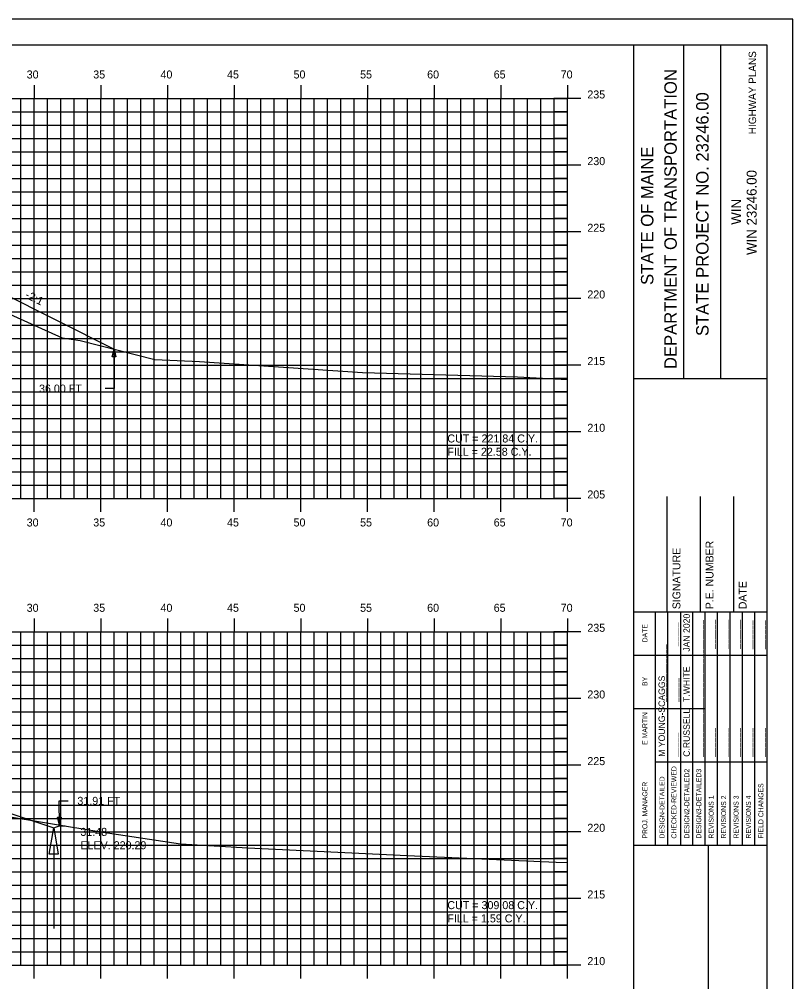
# Model space of a CAD drawing. Extents: x 1137876 to 1138046, y 608981 to 609091.
# Drawn here: x 1137988.1 to 1138046.1, y 609019.1 to 609091.3 of the extents above; entities that cross this region are included whole.
import ezdxf

# ---------------------------------------------------------------- set-up
doc = ezdxf.new("R2010")
doc.units = 0
for name, color, linetype in [('ANNOTATION', 7, 'Continuous'), ('BORDER', 7, 'Continuous'), ('D_Drainage_Ditch_Line', 7, 'Continuous'), ('D_Roadway_SlopeLines', 7, 'Continuous'), ('D_Text_Standard', 7, 'Continuous'), ('H_V ANNOTATION', 7, 'Continuous'), ('HIGHWAY_TITLE', 7, 'Continuous'), ('MAJOR', 7, 'Continuous'), ('MINOR', 7, 'Continuous'), ('PLOT BOUNDARY', 7, 'Continuous'), ('S_Roadway_Centerline', 7, 'Continuous')]:
    doc.layers.add(name, color=color, linetype=linetype)

msp = doc.modelspace()

# ---------------------------------------------------------------- linework, layer by layer
msp.add_lwpolyline([(1137924.31, 609071.229), (1137926.339, 609071.906), (1137929.339, 609072.906), (1137936.714, 609075.364), (1137936.715, 609075.364), (1137948.166, 609075.822), (1137959.166, 609076.042), (1137970.166, 609075.822), (1137977.166, 609075.542), (1137982.083, 609073.084), (1137986.552, 609070.849), (1137995.165, 609066.543)])
at = {"layer": 'BORDER'}
for p, q in [((1138034.166, 608984.335), (1138034.166, 609089.335)), ((1138037.895, 609064.332), (1138037.895, 609089.332)), ((1138040.69, 609064.332), (1138040.69, 609089.332)), ((1138034.167, 609064.329), (1138044.166, 609064.329)), ((1138036.666, 609046.838), (1138036.666, 609055.485)), ((1138039.166, 609046.838), (1138039.166, 609055.485)), ((1138041.666, 609046.838), (1138041.666, 609055.485)), ((1138034.166, 609046.838), (1138044.166, 609046.838)), ((1138034.166, 609029.338), (1138044.166, 609029.338)), ((1138039.757, 608994.338), (1138039.757, 609029.338))]:
    msp.add_line(p, q, dxfattribs=at)
msp.add_lwpolyline([(1137884.166, 608984.335), (1138044.166, 608984.335), (1138044.166, 609089.335), (1137884.166, 609089.335)], close=True, dxfattribs=at)
for points in [[(1138035.781, 609043.588), (1138035.781, 609046.838)], [(1138036.714, 609029.341), (1138036.714, 609046.838)], [(1138037.645, 609046.838), (1138037.645, 609029.341)], [(1138038.577, 609029.341), (1138038.577, 609046.838)], [(1138039.509, 609029.341), (1138039.509, 609046.838)], [(1138040.44, 609029.341), (1138040.44, 609046.838)], [(1138041.372, 609029.341), (1138041.372, 609046.838)], [(1138042.304, 609029.341), (1138042.304, 609046.838)], [(1138043.235, 609029.341), (1138043.235, 609046.838)], [(1138035.782, 609029.341), (1138035.782, 609046.132)], [(1138034.166, 609043.588), (1138044.166, 609043.588)], [(1138034.166, 609039.588), (1138035.782, 609039.588)], [(1138035.781, 609039.588), (1138039.508, 609039.588)], [(1138035.781, 609035.588), (1138044.166, 609035.588)]]:
    msp.add_lwpolyline(points, dxfattribs=at)
at = {"layer": 'D_Drainage_Ditch_Line'}
msp.add_line((1137990.642, 609029.316), (1137990.641, 609023.072), dxfattribs=at)
msp.add_lwpolyline([(1137990.97, 609028.66), (1137990.314, 609028.66), (1137990.642, 609030.628)], close=True, dxfattribs=at)
at = {"layer": 'D_Roadway_SlopeLines'}
for points in [[(1137986.552, 609070.849), (1137995.165, 609066.543)], [(1137984.698, 609032.609), (1137990.642, 609030.628)], [(1137990.642, 609030.628), (1137990.857, 609030.718), (1137991.072, 609030.771), (1137991.287, 609030.789), (1137991.502, 609030.771)]]:
    msp.add_lwpolyline(points, dxfattribs=at)
at = {"layer": 'D_Text_Standard'}
for points in [[(1137995.165, 609066.543), (1137995.184, 609063.575), (1137994.504, 609063.575)], [(1137991.072, 609030.843), (1137991.058, 609032.656), (1137991.738, 609032.656)]]:
    msp.add_lwpolyline(points, dxfattribs=at)
for points in [[(1137995.165, 609066.543), (1137995.314, 609065.961), (1137995.023, 609065.96)], [(1137991.072, 609030.843), (1137990.922, 609031.424), (1137991.213, 609031.426)]]:
    msp.add_lwpolyline(points, close=True, dxfattribs=at)
at = {"layer": 'MAJOR'}
for p, q in [((1137989.166, 609086.337), (1137989.166, 609085.335)), ((1137994.166, 609086.337), (1137994.166, 609085.335)), ((1137999.166, 609086.337), (1137999.166, 609085.335)), ((1138004.166, 609086.337), (1138004.166, 609085.335)), ((1138009.166, 609086.337), (1138009.166, 609085.335)), ((1138014.166, 609086.337), (1138014.166, 609085.335)), ((1138019.166, 609086.337), (1138019.166, 609085.335)), ((1138024.166, 609086.337), (1138024.166, 609085.335)), ((1138029.166, 609086.337), (1138029.166, 609085.335)), ((1137889.166, 609085.335), (1138029.166, 609085.335)), ((1137889.166, 609085.335), (1138029.166, 609085.335)), ((1137989.166, 609055.335), (1137989.166, 609085.335)), ((1137994.166, 609055.335), (1137994.166, 609085.335)), ((1137999.166, 609055.335), (1137999.166, 609085.335)), ((1138004.166, 609055.335), (1138004.166, 609085.335)), ((1138009.166, 609055.335), (1138009.166, 609085.335)), ((1138014.166, 609055.335), (1138014.166, 609085.335)), ((1138019.166, 609055.335), (1138019.166, 609085.335)), ((1138024.166, 609055.335), (1138024.166, 609085.335)), ((1138030.168, 609085.335), (1138028.164, 609085.335)), ((1138029.166, 609055.335), (1138029.166, 609085.335)), ((1138029.166, 609055.335), (1138029.166, 609085.335)), ((1137889.166, 609080.335), (1138029.166, 609080.335)), ((1138030.168, 609080.335), (1138028.164, 609080.335)), ((1137889.166, 609075.335), (1138029.166, 609075.335)), ((1138030.168, 609075.335), (1138028.164, 609075.335)), ((1137889.166, 609070.335), (1138029.166, 609070.335)), ((1138030.168, 609070.335), (1138028.164, 609070.335)), ((1137889.166, 609065.335), (1138029.166, 609065.335)), ((1138030.168, 609065.335), (1138028.164, 609065.335)), ((1137889.166, 609060.335), (1138029.166, 609060.335)), ((1138030.168, 609060.335), (1138028.164, 609060.335)), ((1137889.166, 609055.335), (1138029.166, 609055.335)), ((1137889.166, 609055.335), (1138029.166, 609055.335)), ((1137989.166, 609054.333), (1137989.166, 609055.335)), ((1137994.166, 609054.333), (1137994.166, 609055.335)), ((1137999.166, 609054.333), (1137999.166, 609055.335)), ((1138004.166, 609054.333), (1138004.166, 609055.335)), ((1138009.166, 609054.333), (1138009.166, 609055.335)), ((1138014.166, 609054.333), (1138014.166, 609055.335)), ((1138019.166, 609054.333), (1138019.166, 609055.335)), ((1138024.166, 609054.333), (1138024.166, 609055.335)), ((1138030.168, 609055.335), (1138028.164, 609055.335)), ((1138029.166, 609054.333), (1138029.166, 609055.335)), ((1137989.166, 609046.337), (1137989.166, 609045.335)), ((1137994.166, 609046.337), (1137994.166, 609045.335)), ((1137999.166, 609046.337), (1137999.166, 609045.335)), ((1138004.166, 609046.337), (1138004.166, 609045.335)), ((1138009.166, 609046.337), (1138009.166, 609045.335)), ((1138014.166, 609046.337), (1138014.166, 609045.335)), ((1138019.166, 609046.337), (1138019.166, 609045.335)), ((1138024.166, 609046.337), (1138024.166, 609045.335)), ((1138029.166, 609046.337), (1138029.166, 609045.335)), ((1137889.166, 609045.335), (1138029.166, 609045.335)), ((1137889.166, 609045.335), (1138029.166, 609045.335)), ((1137989.166, 609020.335), (1137989.166, 609045.335)), ((1137994.166, 609020.335), (1137994.166, 609045.335)), ((1137999.166, 609020.335), (1137999.166, 609045.335)), ((1138004.166, 609020.335), (1138004.166, 609045.335)), ((1138009.166, 609020.335), (1138009.166, 609045.335)), ((1138014.166, 609020.335), (1138014.166, 609045.335)), ((1138019.166, 609020.335), (1138019.166, 609045.335)), ((1138024.166, 609020.335), (1138024.166, 609045.335)), ((1138030.168, 609045.335), (1138028.164, 609045.335)), ((1138029.166, 609020.335), (1138029.166, 609045.335)), ((1138029.166, 609020.335), (1138029.166, 609045.335)), ((1137889.166, 609040.335), (1138029.166, 609040.335)), ((1138030.168, 609040.335), (1138028.164, 609040.335)), ((1137889.166, 609035.335), (1138029.166, 609035.335)), ((1138030.168, 609035.335), (1138028.164, 609035.335)), ((1137889.166, 609030.335), (1138029.166, 609030.335)), ((1138030.168, 609030.335), (1138028.164, 609030.335)), ((1137889.166, 609025.335), (1138029.166, 609025.335)), ((1138030.168, 609025.335), (1138028.164, 609025.335)), ((1137889.166, 609020.335), (1138029.166, 609020.335)), ((1137889.166, 609020.335), (1138029.166, 609020.335)), ((1137989.166, 609019.333), (1137989.166, 609020.335)), ((1137994.166, 609019.333), (1137994.166, 609020.335)), ((1137999.166, 609019.333), (1137999.166, 609020.335)), ((1138004.166, 609019.333), (1138004.166, 609020.335)), ((1138009.166, 609019.333), (1138009.166, 609020.335)), ((1138014.166, 609019.333), (1138014.166, 609020.335)), ((1138019.166, 609019.333), (1138019.166, 609020.335)), ((1138024.166, 609019.333), (1138024.166, 609020.335)), ((1138030.168, 609020.335), (1138028.164, 609020.335)), ((1138029.166, 609019.333), (1138029.166, 609020.335))]:
    msp.add_line(p, q, dxfattribs=at)
at = {"layer": 'MINOR'}
for p, q in [((1137988.166, 609055.335), (1137988.166, 609085.335)), ((1137990.166, 609055.335), (1137990.166, 609085.335)), ((1137991.166, 609055.335), (1137991.166, 609085.335)), ((1137992.166, 609055.335), (1137992.166, 609085.335)), ((1137993.166, 609055.335), (1137993.166, 609085.335)), ((1137995.166, 609055.335), (1137995.166, 609085.335)), ((1137996.166, 609055.335), (1137996.166, 609085.335)), ((1137997.166, 609055.335), (1137997.166, 609085.335)), ((1137998.166, 609055.335), (1137998.166, 609085.335)), ((1138000.166, 609055.335), (1138000.166, 609085.335)), ((1138001.166, 609055.335), (1138001.166, 609085.335)), ((1138002.166, 609055.335), (1138002.166, 609085.335)), ((1138003.166, 609055.335), (1138003.166, 609085.335)), ((1138005.166, 609055.335), (1138005.166, 609085.335)), ((1138006.166, 609055.335), (1138006.166, 609085.335)), ((1138007.166, 609055.335), (1138007.166, 609085.335)), ((1138008.166, 609055.335), (1138008.166, 609085.335)), ((1138010.166, 609055.335), (1138010.166, 609085.335)), ((1138011.166, 609055.335), (1138011.166, 609085.335)), ((1138012.166, 609055.335), (1138012.166, 609085.335)), ((1138013.166, 609055.335), (1138013.166, 609085.335)), ((1138015.166, 609055.335), (1138015.166, 609085.335)), ((1138016.166, 609055.335), (1138016.166, 609085.335)), ((1138017.166, 609055.335), (1138017.166, 609085.335)), ((1138018.166, 609055.335), (1138018.166, 609085.335)), ((1138020.166, 609055.335), (1138020.166, 609085.335)), ((1138021.166, 609055.335), (1138021.166, 609085.335)), ((1138022.166, 609055.335), (1138022.166, 609085.335)), ((1138023.166, 609055.335), (1138023.166, 609085.335)), ((1138025.166, 609055.335), (1138025.166, 609085.335)), ((1138026.166, 609055.335), (1138026.166, 609085.335)), ((1138027.166, 609055.335), (1138027.166, 609085.335)), ((1138028.166, 609055.335), (1138028.166, 609085.335)), ((1137889.166, 609084.335), (1138029.166, 609084.335)), ((1138029.166, 609084.335), (1138028.164, 609084.335)), ((1137889.166, 609083.335), (1138029.166, 609083.335)), ((1138029.166, 609083.335), (1138028.164, 609083.335)), ((1137889.166, 609082.335), (1138029.166, 609082.335)), ((1138029.166, 609082.335), (1138028.164, 609082.335)), ((1137889.166, 609081.335), (1138029.166, 609081.335)), ((1138029.166, 609081.335), (1138028.164, 609081.335)), ((1137889.166, 609079.335), (1138029.166, 609079.335)), ((1138029.166, 609079.335), (1138028.164, 609079.335)), ((1137889.166, 609078.335), (1138029.166, 609078.335)), ((1138029.166, 609078.335), (1138028.164, 609078.335)), ((1137889.166, 609077.335), (1138029.166, 609077.335)), ((1138029.166, 609077.335), (1138028.164, 609077.335)), ((1137889.166, 609076.335), (1138029.166, 609076.335)), ((1138029.166, 609076.335), (1138028.164, 609076.335)), ((1137889.166, 609074.335), (1138029.166, 609074.335)), ((1138029.166, 609074.335), (1138028.164, 609074.335)), ((1137889.166, 609073.335), (1138029.166, 609073.335)), ((1138029.166, 609073.335), (1138028.164, 609073.335)), ((1137889.166, 609072.335), (1138029.166, 609072.335)), ((1138029.166, 609072.335), (1138028.164, 609072.335)), ((1137889.166, 609071.335), (1138029.166, 609071.335)), ((1138029.166, 609071.335), (1138028.164, 609071.335)), ((1137889.166, 609069.335), (1138029.166, 609069.335)), ((1138029.166, 609069.335), (1138028.164, 609069.335)), ((1137889.166, 609068.335), (1138029.166, 609068.335)), ((1138029.166, 609068.335), (1138028.164, 609068.335)), ((1137889.166, 609067.335), (1138029.166, 609067.335)), ((1138029.166, 609067.335), (1138028.164, 609067.335)), ((1137889.166, 609066.335), (1138029.166, 609066.335)), ((1138029.166, 609066.335), (1138028.164, 609066.335)), ((1137889.166, 609064.335), (1138029.166, 609064.335)), ((1138029.166, 609064.335), (1138028.164, 609064.335)), ((1137889.166, 609063.335), (1138029.166, 609063.335)), ((1138029.166, 609063.335), (1138028.164, 609063.335)), ((1137889.166, 609062.335), (1138029.166, 609062.335)), ((1138029.166, 609062.335), (1138028.164, 609062.335)), ((1137889.166, 609061.335), (1138029.166, 609061.335)), ((1138029.166, 609061.335), (1138028.164, 609061.335)), ((1137889.166, 609059.335), (1138029.166, 609059.335)), ((1138029.166, 609059.335), (1138028.164, 609059.335)), ((1137889.166, 609058.335), (1138029.166, 609058.335)), ((1138029.166, 609058.335), (1138028.164, 609058.335)), ((1137889.166, 609057.335), (1138029.166, 609057.335)), ((1138029.166, 609057.335), (1138028.164, 609057.335)), ((1137889.166, 609056.335), (1138029.166, 609056.335)), ((1138029.166, 609056.335), (1138028.164, 609056.335)), ((1137988.166, 609020.335), (1137988.166, 609045.335)), ((1137990.166, 609020.335), (1137990.166, 609045.335)), ((1137991.166, 609020.335), (1137991.166, 609045.335)), ((1137992.166, 609020.335), (1137992.166, 609045.335)), ((1137993.166, 609020.335), (1137993.166, 609045.335)), ((1137995.166, 609020.335), (1137995.166, 609045.335)), ((1137996.166, 609020.335), (1137996.166, 609045.335)), ((1137997.166, 609020.335), (1137997.166, 609045.335)), ((1137998.166, 609020.335), (1137998.166, 609045.335)), ((1138000.166, 609020.335), (1138000.166, 609045.335)), ((1138001.166, 609020.335), (1138001.166, 609045.335)), ((1138002.166, 609020.335), (1138002.166, 609045.335)), ((1138003.166, 609020.335), (1138003.166, 609045.335)), ((1138005.166, 609020.335), (1138005.166, 609045.335)), ((1138006.166, 609020.335), (1138006.166, 609045.335)), ((1138007.166, 609020.335), (1138007.166, 609045.335)), ((1138008.166, 609020.335), (1138008.166, 609045.335)), ((1138010.166, 609020.335), (1138010.166, 609045.335)), ((1138011.166, 609020.335), (1138011.166, 609045.335)), ((1138012.166, 609020.335), (1138012.166, 609045.335)), ((1138013.166, 609020.335), (1138013.166, 609045.335)), ((1138015.166, 609020.335), (1138015.166, 609045.335)), ((1138016.166, 609020.335), (1138016.166, 609045.335)), ((1138017.166, 609020.335), (1138017.166, 609045.335)), ((1138018.166, 609020.335), (1138018.166, 609045.335)), ((1138020.166, 609020.335), (1138020.166, 609045.335)), ((1138021.166, 609020.335), (1138021.166, 609045.335)), ((1138022.166, 609020.335), (1138022.166, 609045.335)), ((1138023.166, 609020.335), (1138023.166, 609045.335)), ((1138025.166, 609020.335), (1138025.166, 609045.335)), ((1138026.166, 609020.335), (1138026.166, 609045.335)), ((1138027.166, 609020.335), (1138027.166, 609045.335)), ((1138028.166, 609020.335), (1138028.166, 609045.335)), ((1137889.166, 609044.335), (1138029.166, 609044.335)), ((1138029.166, 609044.335), (1138028.164, 609044.335)), ((1137889.166, 609043.335), (1138029.166, 609043.335)), ((1138029.166, 609043.335), (1138028.164, 609043.335)), ((1137889.166, 609042.335), (1138029.166, 609042.335)), ((1138029.166, 609042.335), (1138028.164, 609042.335)), ((1137889.166, 609041.335), (1138029.166, 609041.335)), ((1138029.166, 609041.335), (1138028.164, 609041.335)), ((1137889.166, 609039.335), (1138029.166, 609039.335)), ((1138029.166, 609039.335), (1138028.164, 609039.335)), ((1137889.166, 609038.335), (1138029.166, 609038.335)), ((1138029.166, 609038.335), (1138028.164, 609038.335)), ((1137889.166, 609037.335), (1138029.166, 609037.335)), ((1138029.166, 609037.335), (1138028.164, 609037.335)), ((1137889.166, 609036.335), (1138029.166, 609036.335)), ((1138029.166, 609036.335), (1138028.164, 609036.335)), ((1137889.166, 609034.335), (1138029.166, 609034.335)), ((1138029.166, 609034.335), (1138028.164, 609034.335)), ((1137889.166, 609033.335), (1138029.166, 609033.335)), ((1138029.166, 609033.335), (1138028.164, 609033.335)), ((1137889.166, 609032.335), (1138029.166, 609032.335)), ((1138029.166, 609032.335), (1138028.164, 609032.335)), ((1137889.166, 609031.335), (1138029.166, 609031.335)), ((1138029.166, 609031.335), (1138028.164, 609031.335)), ((1137889.166, 609029.335), (1138029.166, 609029.335)), ((1138029.166, 609029.335), (1138028.164, 609029.335)), ((1137889.166, 609028.335), (1138029.166, 609028.335)), ((1138029.166, 609028.335), (1138028.164, 609028.335)), ((1137889.166, 609027.335), (1138029.166, 609027.335)), ((1138029.166, 609027.335), (1138028.164, 609027.335)), ((1137889.166, 609026.335), (1138029.166, 609026.335)), ((1138029.166, 609026.335), (1138028.164, 609026.335)), ((1137889.166, 609024.335), (1138029.166, 609024.335)), ((1138029.166, 609024.335), (1138028.164, 609024.335)), ((1137889.166, 609023.335), (1138029.166, 609023.335)), ((1138029.166, 609023.335), (1138028.164, 609023.335)), ((1137889.166, 609022.335), (1138029.166, 609022.335)), ((1138029.166, 609022.335), (1138028.164, 609022.335)), ((1137889.166, 609021.335), (1138029.166, 609021.335)), ((1138029.166, 609021.335), (1138028.164, 609021.335))]:
    msp.add_line(p, q, dxfattribs=at)
at = {"layer": 'PLOT BOUNDARY'}
msp.add_lwpolyline([(1137876.073, 608981.276), (1138046.073, 608981.276), (1138046.073, 609091.276), (1137876.073, 609091.276)], close=True, dxfattribs=at)
at = {"layer": 'S_Roadway_Centerline'}
for points in [[(1137889.166, 609070.313), (1137894.157, 609070.541), (1137907.419, 609071.161), (1137910.439, 609071.192), (1137910.786, 609071.181), (1137926.383, 609071.246), (1137927.333, 609071.573), (1137942.192, 609075.263), (1137946.056, 609075.698), (1137947.752, 609075.86), (1137957.882, 609075.908), (1137959.356, 609075.955), (1137960.699, 609075.902), (1137970.583, 609075.689), (1137973.493, 609075.356), (1137973.722, 609075.319), (1137986.058, 609069.74), (1137991.281, 609067.381), (1137992.629, 609067.183), (1137998.236, 609065.767), (1138001.572, 609065.613), (1138013.791, 609064.771), (1138025.425, 609064.464), (1138029.166, 609064.258)], [(1137986.631, 609031.589), (1137994.165, 609030.324), (1138000.164, 609029.428), (1138005.212, 609029.144), (1138017.15, 609028.548), (1138028.326, 609028.052), (1138029.166, 609028.02)]]:
    msp.add_lwpolyline(points, dxfattribs=at)

# ---------------------------------------------------------------- texts
at = {"layer": 'ANNOTATION'}
msp.add_text('-2:1', height=0.6, rotation=333.43495, dxfattribs=at).set_placement((1137988.447, 609070.419))
at = {"layer": 'BORDER'}
for s, height, p in [('DEPARTMENT OF TRANSPORTATION', 0.93176, (1138037.373, 609065.041)), ('STATE PROJECT NO. 23246.00', 0.93176, (1138039.758, 609067.517)), ('STATE OF MAINE', 0.93176, (1138035.621, 609071.347)), ('WIN 23246.00', 0.74527, (1138043.362, 609073.596)), ('WIN', 0.7453, (1138042.203, 609075.865)), ('SIGNATURE', 0.5906, (1138037.647, 609047.03)), ('P.E. NUMBER', 0.59055, (1138040.127, 609047.03)), ('DATE', 0.5906, (1138042.607, 609047.03)), ('JAN 2020', 0.4845, (1138038.352, 609043.843)), ('DATE', 0.3714, (1138035.17, 609044.544)), ('_____', 0.4845, (1138037.384, 609044.243)), ('______', 0.4845, (1138039.247, 609044.063)), ('______', 0.4845, (1138040.179, 609044.065)), ('______', 0.4845, (1138041.11, 609044.067)), ('______', 0.4845, (1138042.042, 609044.067)), ('______', 0.4845, (1138042.974, 609044.036)), ('______', 0.4845, (1138043.905, 609044.036)), ('____________', 0.48455, (1138036.489, 609040.073)), ('____________', 0.48455, (1138039.247, 609040.073)), ('T.WHITE', 0.4845, (1138038.352, 609040.073)), ('BY', 0.3714, (1138035.17, 609041.273)), ('M YOUNG-SCAGGS', 0.48455, (1138036.489, 609035.961)), ('_____', 0.4845, (1138037.421, 609040.073)), ('____________', 0.48455, (1138039.247, 609035.961)), ('C.RUSSELL', 0.4845, (1138038.352, 609035.961)), ('E MARTIN', 0.3727, (1138035.17, 609036.855)), ('_____', 0.4845, (1138037.384, 609035.961)), ('______', 0.4845, (1138040.179, 609035.961)), ('______', 0.4845, (1138041.11, 609035.961)), ('______', 0.4845, (1138042.042, 609035.961)), ('______', 0.4845, (1138042.974, 609035.961)), ('______', 0.4845, (1138043.905, 609035.961)), ('CHECKED-REVIEWED', 0.37275, (1138037.347, 609029.826)), ('DESIGN2-DETAILED2', 0.37275, (1138038.316, 609029.826)), ('DESIGN3-DETAILED3', 0.37275, (1138039.211, 609029.826)), ('DESIGN-DETAILED', 0.37275, (1138036.453, 609029.826)), ('PROJ. MANAGER', 0.37275, (1138035.17, 609029.826)), ('FIELD CHANGES', 0.37275, (1138043.869, 609029.826)), ('REVISIONS 1', 0.37275, (1138040.142, 609029.826)), ('REVISIONS 2', 0.37275, (1138041.074, 609029.826)), ('REVISIONS 3', 0.37275, (1138042.006, 609029.826)), ('REVISIONS 4', 0.37275, (1138042.937, 609029.826))]:
    msp.add_text(s, height=height, rotation=90, dxfattribs=at).set_placement(p)
at = {"layer": 'D_Text_Standard'}
for s, p in [('36.00 FT', (1137989.542, 609063.275)), ('CUT = 221.84 C.Y.', (1138020.166, 609059.535)), ('FILL = 22.58 C.Y.', (1138020.166, 609058.539)), ('31.91 FT', (1137992.418, 609032.356)), ('31.48', (1137992.642, 609030.028)), ('ELEV. 220.29', (1137992.642, 609029.026)), ('CUT = 309.08 C.Y.', (1138020.166, 609024.535)), ('FILL = 1.59 C.Y.', (1138020.166, 609023.539))]:
    msp.add_text(s, height=0.6, dxfattribs=at).set_placement(p)
at = {"layer": 'H_V ANNOTATION'}
for s, p in [('30', (1137988.615, 609086.835)), ('35', (1137993.607, 609086.835)), ('40', (1137998.652, 609086.835)), ('45', (1138003.644, 609086.835)), ('50', (1138008.631, 609086.835)), ('55', (1138013.623, 609086.835)), ('60', (1138018.652, 609086.835)), ('65', (1138023.644, 609086.835)), ('70', (1138028.668, 609086.835)), ('235', (1138030.666, 609085.335)), ('230', (1138030.666, 609080.335)), ('225', (1138030.666, 609075.335)), ('220', (1138030.666, 609070.335)), ('215', (1138030.666, 609065.335)), ('210', (1138030.666, 609060.335)), ('205', (1138030.666, 609055.335)), ('30', (1137988.615, 609053.235)), ('35', (1137993.607, 609053.235)), ('40', (1137998.652, 609053.235)), ('45', (1138003.644, 609053.235)), ('50', (1138008.631, 609053.235)), ('55', (1138013.623, 609053.235)), ('60', (1138018.652, 609053.235)), ('65', (1138023.644, 609053.235)), ('70', (1138028.668, 609053.235)), ('30', (1137988.615, 609046.835)), ('35', (1137993.607, 609046.835)), ('40', (1137998.652, 609046.835)), ('45', (1138003.644, 609046.835)), ('50', (1138008.631, 609046.835)), ('55', (1138013.623, 609046.835)), ('60', (1138018.652, 609046.835)), ('65', (1138023.644, 609046.835)), ('70', (1138028.668, 609046.835)), ('235', (1138030.666, 609045.335)), ('230', (1138030.666, 609040.335)), ('225', (1138030.666, 609035.335)), ('220', (1138030.666, 609030.335)), ('215', (1138030.666, 609025.335)), ('210', (1138030.666, 609020.335))]:
    msp.add_text(s, height=0.6, dxfattribs=at).set_placement(p)
at = {"layer": 'HIGHWAY_TITLE'}
msp.add_text('HIGHWAY PLANS', height=0.55901, rotation=90, dxfattribs=at).set_placement((1138043.324, 609082.65))

doc.saveas('drawing.dxf')
